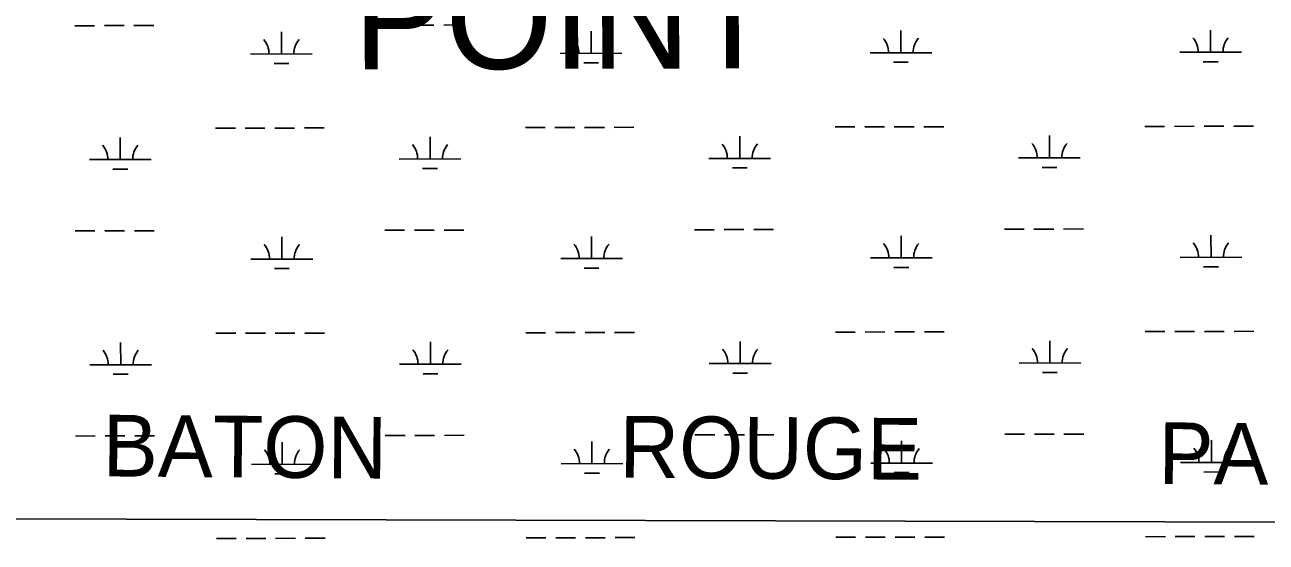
# Model space of a CAD drawing. Extents: x 3329297 to 3367176, y 649250 to 674653.
# Drawn here: x 3334498 to 3336510, y 662998 to 663837 of the extents above; entities that cross this region are included whole.
import ezdxf

# ---------------------------------------------------------------- set-up
doc = ezdxf.new("R2010")
doc.units = 0
for name, color, linetype in [('V-RIVR-EDGE', 7, 'Continuous'), ('V-TOPO-BNDY', 7, 'Continuous'), ('V-TOPO-GNAM-IDEN', 7, 'Continuous'), ('V-WETL-SWMP', 7, 'Continuous')]:
    doc.layers.add(name, color=color, linetype=linetype)

msp = doc.modelspace()

# ---------------------------------------------------------------- linework, layer by layer
at = {"layer": 'V-RIVR-EDGE'}
msp.add_spline([(3333408.7, 669402.3), (3333456.2, 669390.7), (3333480.6, 669386.5), (3333498.4, 669381.9), (3333510.9, 669380.2), (3333522.1, 669375.2), (3333537.8, 669370.2), (3333569.3, 669364.3), (3333591.6, 669358.9), (3333623.1, 669349.7), (3333650.9, 669341.3), (3333676.1, 669333), (3333726.3, 669319.2), (3333778.9, 669302), (3333791.7, 669299.5), (3333813.6, 669293.3), (3333833.9, 669285.7), (3333853.8, 669277.4), (3333866.2, 669277.4), (3333927.5, 669258.6), (3333978.9, 669241), (3334054.7, 669220.1), (3334082, 669212.6), (3334104.4, 669205.9), (3334133.4, 669195.1), (3334212.1, 669170), (3334258.9, 669154.5), (3334287.5, 669144.9), (3334323.9, 669134.5), (3334362.8, 669121.1), (3334397.6, 669109.4), (3334435.3, 669094.8), (3334441.9, 669091.5), (3334451.9, 669089.8), (3334461, 669084), (3334464.7, 669082.7), (3334470.5, 669083.6), (3334476.3, 669080.2), (3334476.7, 669076.1), (3334486.6, 669072.7), (3334503.2, 669071.9), (3334523.5, 669067.3), (3334538.4, 669061.4), (3334550.4, 669055.2), (3334564.9, 669046.8), (3334575.7, 669042.7), (3334598.9, 669036.4), (3334626.2, 669030.9), (3334690.8, 669018.8), (3334721.1, 669015.8), (3334733.1, 669015.8), (3334745.1, 669011.2), (3334755.1, 669009.5), (3334769.6, 669008.6), (3334791.1, 669004.4), (3334799.8, 669004.4), (3334813.5, 669004.8), (3334832.6, 668999.8), (3334841.7, 668998.5), (3334844.6, 668994.8), (3334857, 668990.2), (3334864, 668983.9), (3334870.2, 668977.7), (3334876.8, 668970.2), (3334882.2, 668968.6), (3334894.6, 668965.6), (3334904.2, 668965.6), (3334918.3, 668964.3), (3334926.6, 668963.5), (3334936.1, 668958.5), (3334945.2, 668949.3), (3334956.8, 668941), (3334959.7, 668941.4), (3334971.7, 668941.4), (3334983.3, 668941.8), (3334993.2, 668938.9), (3335003.6, 668932.2), (3335011.4, 668925.1), (3335021.8, 668920.1), (3335034.2, 668916), (3335054.9, 668911.8), (3335057, 668908.9), (3335064.8, 668903.9), (3335073.5, 668900.1), (3335081, 668898), (3335087.6, 668898), (3335095.1, 668898), (3335097.6, 668895.1), (3335105, 668888.4), (3335114.1, 668882.2), (3335138.1, 668873), (3335159.7, 668864.2), (3335185.7, 668850.5), (3335195.2, 668838.9), (3335211, 668830.1), (3335229.2, 668825.5), (3335249.9, 668817.6), (3335252.4, 668811.4), (3335261.5, 668805.6), (3335272.7, 668798.5), (3335296.3, 668792.6), (3335327.3, 668778.4), (3335359.2, 668761.8), (3335399.3, 668739.7), (3335432.5, 668723.5), (3335466.4, 668708.1), (3335508.6, 668689.3), (3335535.5, 668674.3), (3335584, 668653.1), (3335614.6, 668638.1), (3335645.3, 668624.7), (3335682.1, 668600.6), (3335715.2, 668580.6), (3335752.5, 668561.5), (3335771.9, 668553.1), (3335793.9, 668548.5), (3335846.4, 668524.7), (3335870.9, 668514.7), (3335887.9, 668509.3), (3335894.9, 668501), (3335912.7, 668488.1), (3335927.6, 668478.1), (3335958.6, 668466.4), (3335986.8, 668452.7), (3336001.3, 668442.7), (3336018.7, 668434.4), (3336038.9, 668426.9), (3336117.2, 668387.3), (3336184.2, 668349), (3336223.1, 668326.5), (3336257.5, 668305.7), (3336289.4, 668284.5), (3336317.1, 668269.5), (3336332.8, 668261.6), (3336456.6, 668198.7), (3336509.2, 668170.8), (3336541.4, 668152.9), (3336585.7, 668130), (3336625.9, 668110.8), (3336652.8, 668097.9), (3336753.4, 668040), (3336798.1, 668013.8), (3336819.6, 668001.3), (3336844, 667986.8), (3336862.2, 667973.9), (3336893.7, 667952.2), (3336928, 667933.1), (3336960.3, 667914.8), (3336990.5, 667894.8), (3337029.4, 667867.8), (3337069.1, 667842.4), (3337101, 667829.5), (3337126.7, 667818.2), (3337166, 667790.3), (3337200.4, 667767.9), (3337228.5, 667747.5), (3337263.3, 667726.3), (3337288.9, 667709.2), (3337372.5, 667657.2), (3337387.8, 667642.6), (3337413.9, 667621.9), (3337448.6, 667598.6), (3337473.4, 667578.6), (3337509, 667550.7), (3337579.4, 667503.3), (3337621.1, 667469.6), (3337665, 667431), (3337708, 667391.1), (3337739.8, 667359.1), (3337772.9, 667327.1), (3337812.2, 667288.5), (3337827.1, 667271.4), (3337829.5, 667264.4), (3337842.8, 667251.5), (3337873.4, 667227.8), (3337886.2, 667214.9), (3337903.2, 667197.9), (3337949.4, 667144.7), (3337971.4, 667123.5), (3337996.2, 667096.5), (3338024.3, 667069.9), (3338047, 667044.6), (3338075.5, 667011.8), (3338104.9, 666976.9), (3338113.6, 666965.2), (3338176.8, 666889.6), (3338206.1, 666850.2), (3338224.3, 666825.3), (3338246.2, 666798.3), (3338263.5, 666774.2), (3338301.9, 666718.6), (3338311.9, 666704.5), (3338328, 666683.3), (3338335.4, 666667.9), (3338348.6, 666644.3), (3338362.6, 666627.2), (3338385.4, 666599.4), (3338404.4, 666574.5), (3338412.6, 666562), (3338414.7, 666551.3), (3338422.1, 666533), (3338443.1, 666494), (3338455.9, 666472), (3338475.4, 666449.6), (3338483.2, 666442.9), (3338498.1, 666425), (3338521.6, 666381.9), (3338562.5, 666317.5), (3338585.6, 666290.5), (3338600.5, 666260.7), (3338619.9, 666220), (3338640.9, 666179.7), (3338652.5, 666165.2), (3338660.7, 666148.6), (3338709, 666053.1), (3338735.4, 666007.5), (3338756.4, 665971.4), (3338777.1, 665937.3), (3338810.1, 665887.1), (3338828.7, 665846.4), (3338853.8, 665796.6), (3338873.6, 665751.8), (3338895.1, 665712.8), (3338903.7, 665692.1), (3338916.5, 665665.9), (3338933.8, 665635.2), (3338944.1, 665609.5), (3338956.5, 665578.8), (3338961.9, 665565.5), (3338976.7, 665543.1), (3338985, 665527.7), (3338995.3, 665511.1), (3339011.8, 665472.1), (3339026.6, 665438.9), (3339039.8, 665412.8), (3339047.6, 665382.9), (3339085.5, 665290), (3339099.5, 665253.9), (3339113.5, 665222.8), (3339126.3, 665192.5), (3339138.7, 665160.5), (3339164.2, 665092.5), (3339180.3, 665056), (3339203.7, 664990.8), (3339215.7, 664956.4), (3339231.3, 664897.5), (3339241.1, 664863.5), (3339253.9, 664825.8), (3339262.1, 664798.4), (3339275.3, 664761.9), (3339290.5, 664724.5), (3339306.2, 664692.2), (3339319, 664656.5), (3339324.3, 664636.6), (3339336.6, 664597.2), (3339352.3, 664567.7), (3339365.5, 664538.2), (3339372.1, 664519.6), (3339374.1, 664493), (3339373.2, 664478.9), (3339373.2, 664471.1), (3339377.3, 664449.9), (3339393.8, 664419.2), (3339410.3, 664384.8), (3339423.5, 664344.9), (3339458.5, 664257.4), (3339470, 664219.2), (3339470.4, 664207.2), (3339477.8, 664185.7), (3339481.1, 664164.9), (3339486.4, 664140), (3339490.1, 664124.3), (3339499.6, 664107.3), (3339512.7, 664069.9), (3339523.8, 664028.4), (3339527.5, 663998.2), (3339528.2, 663969.6), (3339525.7, 663951.8), (3339522.4, 663945.6), (3339521.1, 663939.3), (3339524, 663925.2), (3339554.1, 663875), (3339569.4, 663836), (3339574.3, 663803.7), (3339577.1, 663774.2), (3339586.9, 663730.7), (3339599.7, 663691.3), (3339610.3, 663646.9), (3339623.1, 663615.8), (3339630.5, 663595.9), (3339633.8, 663595.9), (3339643, 663599.2), (3339643, 663594.2), (3339646.2, 663566), (3339654.4, 663535.7), (3339664.3, 663503.8), (3339677, 663465.2), (3339691.9, 663427), (3339697.2, 663406.7), (3339697.2, 663392.2), (3339697.1, 663381), (3339704.9, 663354.5), (3339710.7, 663325.4), (3339723.8, 663284.4), (3339738.7, 663247.4), (3339746.1, 663222.6), (3339747.7, 663203.1), (3339746.4, 663183.6), (3339745.5, 663154.6), (3339745, 663130.5), (3339742.9, 663119.4), (3339739.6, 663107.3), (3339737, 663082.5), (3339735.3, 663062.2), (3339736.9, 663039.8), (3339742.2, 663016.6), (3339743.9, 663011.6), (3339748, 663011.6), (3339751.8, 663009.5), (3339753.8, 663002.4), (3339760, 662996.6), (3339761.2, 662990.8), (3339763.7, 662975.9), (3339763.2, 662954.8), (3339760.7, 662930.3), (3339757.8, 662927.8), (3339749.1, 662927.4), (3339743.3, 662927.4), (3339738.7, 662924.1), (3339735, 662917.9), (3339730.4, 662915.9), (3339727.5, 662912.2), (3339727.1, 662907.6), (3339732.4, 662900.1), (3339737.4, 662884.4), (3339741.9, 662869.4), (3339745.2, 662866.1), (3339748.1, 662867.3), (3339750.6, 662877.3), (3339752.7, 662878.9), (3339754.3, 662875.6), (3339755.6, 662867.7), (3339761.7, 662859), (3339764.2, 662850.7), (3339762.5, 662844.1), (3339761.7, 662822.1), (3339758.3, 662812.6), (3339756.6, 662801.8), (3339759.5, 662784), (3339757.4, 662779.4), (3339754.9, 662768.7), (3339755.3, 662757.1), (3339757.7, 662749.6), (3339761.9, 662739.6), (3339755.6, 662731), (3339746.5, 662711.1), (3339737.7, 662704.1), (3339732.8, 662703.2), (3339730.3, 662699.9), (3339733.6, 662689.6), (3339736.8, 662677.1), (3339737.2, 662668), (3339731.8, 662659.3), (3339726.4, 662644.4), (3339724.3, 662641.1), (3339729.7, 662633.2), (3339729.7, 662627.4), (3339727.2, 662625.3), (3339721.8, 662625.8), (3339721.8, 662615.4), (3339723, 662597.2), (3339722.9, 662560.7), (3339725.3, 662535.4), (3339725.3, 662520.5), (3339726.8, 662486.5), (3339724.3, 662463.3), (3339713, 662438.4), (3339703.9, 662416.9), (3339699.7, 662391.6), (3339692.9, 662333.2), (3339688.2, 662298), (3339687.4, 662274.4), (3339683.6, 662256.1), (3339676.1, 662240), (3339666.1, 662216.8), (3339659.8, 662192.8), (3339656.8, 662171.6), (3339654.7, 662126.1), (3339650.4, 662090.8), (3339644.5, 662058.5), (3339643.7, 662039.5), (3339638.2, 662015.4), (3339634.4, 661998.4), (3339628.6, 661971.9), (3339619, 661945.8), (3339616.5, 661933), (3339617.2, 661907.3), (3339619.6, 661875), (3339617.1, 661854.7), (3339612.9, 661845.6), (3339610.8, 661836.4), (3339610, 661829.8), (3339610, 661820.3), (3339609.9, 661810.7), (3339603.7, 661804.1), (3339600.8, 661799.6), (3339598.7, 661785.1), (3339594.9, 661775.6), (3339590.3, 661759.4), (3339588.6, 661741.2), (3339585.7, 661733.3), (3339580.7, 661727.5), (3339574.1, 661723.8), (3339572.8, 661715.9), (3339571.9, 661693.5), (3339564, 661655), (3339553.9, 661613.6), (3339540.6, 661574.7), (3339527.6, 661533.7), (3339508.4, 661497.2), (3339490.1, 661455.8), (3339486.8, 661446.7), (3339487.1, 661432.6), (3339486.3, 661412.3), (3339484.6, 661404), (3339476.7, 661391.6), (3339467.9, 661378.8), (3339453, 661365.1), (3339446.8, 661363.5), (3339441, 661363.1), (3339433.9, 661354.8), (3339423.5, 661346.2), (3339398.2, 661334.6), (3339381.2, 661326.8), (3339370, 661319.8), (3339357.5, 661305.3), (3339344.6, 661280), (3339333, 661269.7), (3339320.9, 661263.5), (3339313.9, 661263.1), (3339310.2, 661266), (3339308.1, 661271.8), (3339302.7, 661282.2), (3339298.6, 661286.4), (3339290.7, 661288.9), (3339284.9, 661288.9), (3339275, 661285.6), (3339261.3, 661273.2), (3339255.5, 661266.6), (3339248.8, 661265.8), (3339234.7, 661264.6), (3339224.4, 661264.2), (3339216.5, 661259.2), (3339211.9, 661252.2), (3339209.4, 661248.5), (3339211, 661240.6), (3339215.6, 661229.4), (3339215.5, 661208.2), (3339213.4, 661191.2), (3339208.8, 661185), (3339198.8, 661169.3), (3339191, 661161.9), (3339179.3, 661161.1), (3339154.5, 661165.7), (3339128, 661171.1), (3339111.4, 661176.2), (3339105.2, 661176.2), (3339096.9, 661174.1), (3339090.7, 661168.7), (3339085.7, 661157.2), (3339071.9, 661143.1), (3339054.9, 661129.9), (3339020.1, 661118.8), (3338993.5, 661110.1), (3338978.6, 661099.8), (3338965.3, 661086.2), (3338953.6, 661064.6), (3338937.4, 661039)], degree=3, dxfattribs=at)
at = {"layer": 'V-TOPO-BNDY'}
msp.add_line((3338846.4, 663024.7), (3333417.7, 663038.8), dxfattribs=at)
at = {"layer": 'V-WETL-SWMP'}
for p, q in [((3334579.3, 663835.9), (3334611.3, 663835.9)), ((3334627.3, 663836), (3334659.3, 663836)), ((3334675.3, 663836), (3334707.3, 663836.1)), ((3334914.2, 663790.1), (3334914.2, 663826.1)), ((3335081.2, 663836.8), (3335113.2, 663836.9)), ((3335129.2, 663836.9), (3335161.2, 663837)), ((3335177.2, 663837), (3335209.2, 663837.1)), ((3335416.1, 663791), (3335416.1, 663827)), ((3335918, 663792), (3335918, 663828)), ((3336420, 663792.9), (3336419.9, 663828.9)), ((3334864.2, 663790), (3334964.2, 663790.2)), ((3335366.1, 663790.9), (3335466.1, 663791.1)), ((3335868, 663791.9), (3335968, 663792.1)), ((3336370, 663792.8), (3336470, 663793)), ((3334902.3, 663774.6), (3334926.3, 663774.7)), ((3335404.2, 663775.6), (3335428.2, 663775.6)), ((3335906.1, 663776.5), (3335930.1, 663776.6)), ((3336408, 663777.5), (3336432, 663777.5)), ((3334807.6, 663669.8), (3334839.6, 663669.9)), ((3334855.6, 663669.9), (3334887.6, 663669.9)), ((3334903.6, 663670), (3334935.6, 663670)), ((3334951.6, 663670.1), (3334983.6, 663670.1)), ((3335309.5, 663670.7), (3335341.5, 663670.8)), ((3335357.5, 663670.8), (3335389.5, 663670.9)), ((3335405.5, 663670.9), (3335437.5, 663671)), ((3335453.5, 663671), (3335485.5, 663671.1)), ((3335811.4, 663671.7), (3335843.4, 663671.8)), ((3335859.4, 663671.8), (3335891.4, 663671.8)), ((3335907.4, 663671.9), (3335939.4, 663671.9)), ((3335955.4, 663672), (3335987.4, 663672)), ((3336313.3, 663672.6), (3336345.3, 663672.7)), ((3336361.3, 663672.7), (3336393.3, 663672.8)), ((3336409.3, 663672.8), (3336441.3, 663672.9)), ((3336457.3, 663672.9), (3336489.3, 663673)), ((3334653.1, 663618.8), (3334653.1, 663654.8)), ((3335155, 663619.7), (3335155, 663655.7)), ((3335656.9, 663620.7), (3335656.9, 663656.7)), ((3336158.8, 663621.6), (3336158.8, 663657.6)), ((3334603.1, 663618.7), (3334703.1, 663618.9)), ((3335105, 663619.6), (3335205, 663619.8)), ((3335606.9, 663620.6), (3335706.9, 663620.8)), ((3335645, 663605.2), (3335669, 663605.2)), ((3336108.8, 663621.5), (3336208.8, 663621.7)), ((3336146.9, 663606.2), (3336170.9, 663606.2)), ((3334641.2, 663603.3), (3334665.2, 663603.4)), ((3335143.1, 663604.3), (3335167.1, 663604.3)), ((3335129.8, 663504.2), (3335161.8, 663504.3)), ((3335177.8, 663504.3), (3335209.8, 663504.4)), ((3335583.7, 663505.1), (3335615.7, 663505.1)), ((3335631.7, 663505.2), (3335663.7, 663505.2)), ((3335679.7, 663505.3), (3335711.7, 663505.3)), ((3336085.7, 663506), (3336117.7, 663506.1)), ((3336133.7, 663506.1), (3336165.7, 663506.2)), ((3336181.7, 663506.2), (3336213.7, 663506.3)), ((3334579.9, 663503.2), (3334611.9, 663503.3)), ((3334627.9, 663503.3), (3334659.9, 663503.3)), ((3334675.9, 663503.4), (3334707.9, 663503.4)), ((3334914.9, 663457.4), (3334914.8, 663493.4)), ((3335081.8, 663504.1), (3335113.8, 663504.2)), ((3335416.8, 663458.3), (3335416.7, 663494.3)), ((3335918.7, 663459.3), (3335918.6, 663495.3)), ((3336420.6, 663460.2), (3336420.5, 663496.2)), ((3334864.9, 663457.3), (3334964.9, 663457.5)), ((3335366.8, 663458.2), (3335466.8, 663458.4)), ((3335868.7, 663459.2), (3335968.7, 663459.4)), ((3335906.7, 663443.8), (3335930.7, 663443.9)), ((3336370.6, 663460.1), (3336470.6, 663460.3)), ((3336408.6, 663444.8), (3336432.6, 663444.8)), ((3334902.9, 663441.9), (3334926.9, 663442)), ((3335404.8, 663442.9), (3335428.8, 663442.9)), ((3334808.2, 663337.1), (3334840.2, 663337.2)), ((3334856.2, 663337.2), (3334888.2, 663337.3)), ((3334904.2, 663337.3), (3334936.2, 663337.4)), ((3334952.2, 663337.4), (3334984.2, 663337.5)), ((3335310.2, 663338.1), (3335342.2, 663338.1)), ((3335358.2, 663338.2), (3335390.2, 663338.2)), ((3335406.2, 663338.2), (3335438.2, 663338.3)), ((3335454.2, 663338.3), (3335486.2, 663338.4)), ((3335657.6, 663288), (3335657.5, 663324)), ((3335812.1, 663339), (3335844.1, 663339.1)), ((3335860.1, 663339.1), (3335892.1, 663339.2)), ((3335908.1, 663339.2), (3335940.1, 663339.3)), ((3335956.1, 663339.3), (3335988.1, 663339.3)), ((3336159.5, 663288.9), (3336159.4, 663324.9)), ((3336314, 663340), (3336346, 663340)), ((3336362, 663340.1), (3336394, 663340.1)), ((3336410, 663340.1), (3336442, 663340.2)), ((3336458, 663340.2), (3336490, 663340.3)), ((3334653.8, 663286.1), (3334653.7, 663322.1)), ((3335155.7, 663287), (3335155.6, 663323)), ((3334603.8, 663286), (3334703.8, 663286.2)), ((3335105.7, 663286.9), (3335205.7, 663287.1)), ((3335607.6, 663287.9), (3335707.6, 663288.1)), ((3336109.5, 663288.8), (3336209.5, 663289)), ((3334641.8, 663270.6), (3334665.8, 663270.7)), ((3335143.7, 663271.6), (3335167.7, 663271.6)), ((3335645.6, 663272.5), (3335669.6, 663272.6)), ((3336147.5, 663273.5), (3336171.5, 663273.5)), ((3334580.6, 663170.5), (3334612.6, 663170.6)), ((3334628.6, 663170.6), (3334660.6, 663170.7)), ((3334676.6, 663170.7), (3334708.6, 663170.8)), ((3335082.5, 663171.5), (3335114.5, 663171.5)), ((3335130.5, 663171.6), (3335162.5, 663171.6)), ((3335178.5, 663171.6), (3335210.5, 663171.7)), ((3335584.4, 663172.4), (3335616.4, 663172.5)), ((3335632.4, 663172.5), (3335664.4, 663172.6)), ((3335680.4, 663172.6), (3335712.4, 663172.7)), ((3335919.3, 663126.6), (3335919.2, 663162.6)), ((3336086.3, 663173.4), (3336118.3, 663173.4)), ((3336134.3, 663173.5), (3336166.3, 663173.5)), ((3336182.3, 663173.5), (3336214.3, 663173.6)), ((3336421.2, 663127.6), (3336421.1, 663163.6)), ((3334915.5, 663124.7), (3334915.4, 663160.7)), ((3335417.4, 663125.7), (3335417.3, 663161.7)), ((3334865.5, 663124.6), (3334965.5, 663124.8)), ((3335367.4, 663125.6), (3335467.4, 663125.8)), ((3335869.3, 663126.5), (3335969.3, 663126.7)), ((3336371.2, 663127.5), (3336471.2, 663127.7)), ((3334903.5, 663109.3), (3334927.5, 663109.3)), ((3335405.4, 663110.2), (3335429.4, 663110.3)), ((3335907.3, 663111.2), (3335931.3, 663111.2)), ((3336409.2, 663112.1), (3336433.2, 663112.2)), ((3334808.9, 663004.4), (3334840.9, 663004.5)), ((3334856.9, 663004.5), (3334888.9, 663004.6)), ((3334904.9, 663004.6), (3334936.9, 663004.7)), ((3334952.9, 663004.7), (3334984.9, 663004.8)), ((3335310.8, 663005.4), (3335342.8, 663005.5)), ((3335358.8, 663005.5), (3335390.8, 663005.5)), ((3335406.8, 663005.6), (3335438.8, 663005.6)), ((3335454.8, 663005.7), (3335486.8, 663005.7)), ((3335812.7, 663006.3), (3335844.7, 663006.4)), ((3335860.7, 663006.4), (3335892.7, 663006.5)), ((3335908.7, 663006.5), (3335940.7, 663006.6)), ((3335956.7, 663006.6), (3335988.7, 663006.7)), ((3336314.6, 663007.3), (3336346.6, 663007.4)), ((3336362.6, 663007.4), (3336394.6, 663007.4)), ((3336410.6, 663007.5), (3336442.6, 663007.5)), ((3336458.6, 663007.6), (3336490.6, 663007.6))]:
    msp.add_line(p, q, dxfattribs=at)
for centre, start, end in [((3334859, 663790.4), 359.3365, 40.8801), ((3334969.5, 663790.6), 139.3365, 180.8801), ((3335360.9, 663791.4), 359.3365, 40.8801), ((3335471.4, 663791.6), 139.3365, 180.8801), ((3335862.8, 663792.3), 359.3365, 40.8801), ((3335973.3, 663792.5), 139.3365, 180.8801), ((3336364.7, 663793.3), 359.3365, 40.8801), ((3336475.2, 663793.5), 139.3365, 180.8801), ((3336103.6, 663622), 359.3365, 40.8801), ((3336214.1, 663622.2), 139.3365, 180.8801), ((3334597.9, 663619.1), 359.3365, 40.8801), ((3334708.4, 663619.3), 139.3365, 180.8801), ((3335099.8, 663620.1), 359.3365, 40.8801), ((3335210.3, 663620.3), 139.3365, 180.8801), ((3335601.7, 663621), 359.3365, 40.8801), ((3335712.2, 663621.2), 139.3365, 180.8801), ((3334859.6, 663457.8), 359.3365, 40.8801), ((3334970.1, 663458), 139.3365, 180.8801), ((3335361.5, 663458.7), 359.3365, 40.8801), ((3335472, 663458.9), 139.3365, 180.8801), ((3335863.4, 663459.7), 359.3365, 40.8801), ((3335973.9, 663459.9), 139.3365, 180.8801), ((3336365.3, 663460.6), 359.3365, 40.8801), ((3336475.8, 663460.8), 139.3365, 180.8801), ((3334598.5, 663286.5), 359.3365, 40.8801), ((3334709, 663286.7), 139.3365, 180.8801), ((3335100.4, 663287.4), 359.3365, 40.8801), ((3335210.9, 663287.6), 139.3365, 180.8801), ((3335602.3, 663288.4), 359.3365, 40.8801), ((3335712.8, 663288.6), 139.3365, 180.8801), ((3336104.2, 663289.3), 359.3365, 40.8801), ((3336214.7, 663289.5), 139.3365, 180.8801), ((3334860.2, 663125.1), 359.3365, 40.8801), ((3334970.7, 663125.3), 139.3365, 180.8801), ((3335362.2, 663126), 359.3365, 40.8801), ((3335472.6, 663126.2), 139.3365, 180.8801), ((3335864.1, 663127), 359.3365, 40.8801), ((3335974.5, 663127.2), 139.3365, 180.8801), ((3336366, 663127.9), 359.3365, 40.8801), ((3336476.5, 663128.1), 139.3365, 180.8801)]:
    msp.add_arc(centre, 35.2, start, end, dxfattribs=at)

# ---------------------------------------------------------------- texts
at = {"layer": 'V-TOPO-GNAM-IDEN'}
for s, height, rotation, p in [('POINT', 167, 0.1169, (3335031.1, 663765.3)), ('BATON', 100, 359.5486, (3334624.4, 663105.1)), ('ROUGE', 100, 359.5486, (3335461.7, 663103.3)), ('PARISH', 100, 359.5486, (3336335.1, 663092.8))]:
    msp.add_text(s, height=height, rotation=rotation, dxfattribs=at).set_placement(p)

doc.saveas('drawing.dxf')
